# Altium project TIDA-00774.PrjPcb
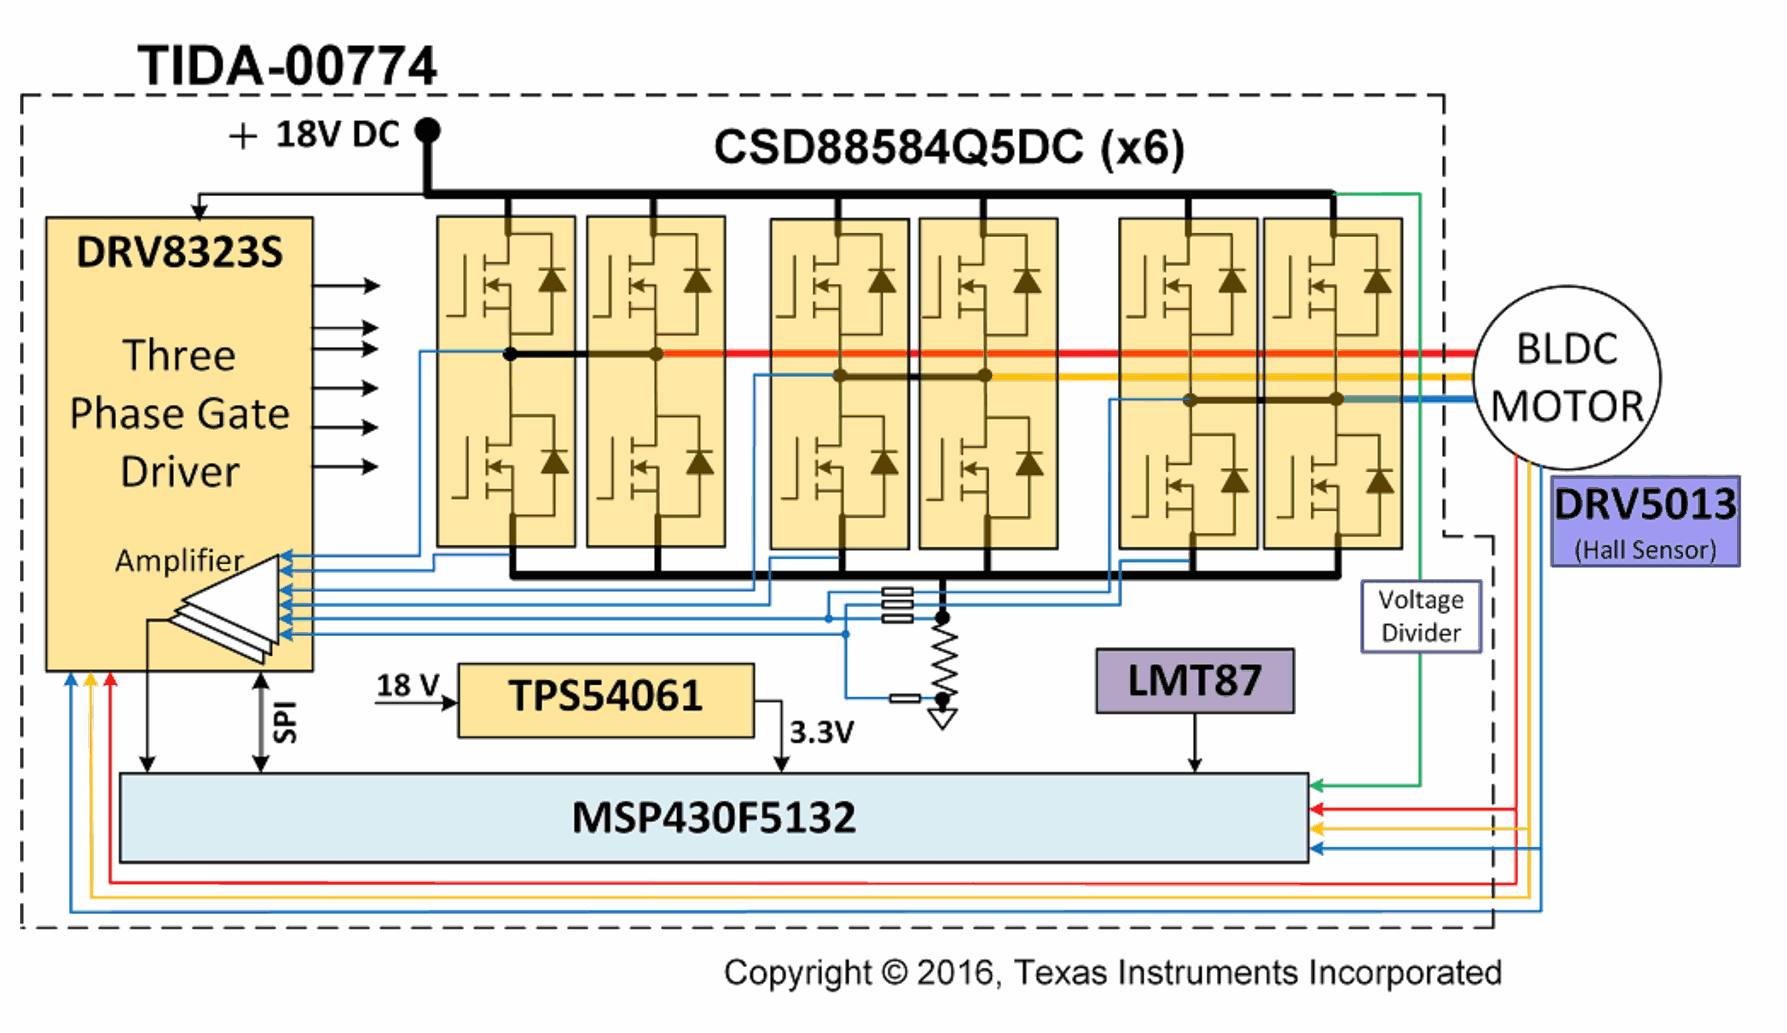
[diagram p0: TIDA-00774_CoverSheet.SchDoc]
CopyrightYear: 2016; EVM_orderable: N/A; PCB_Layout: Avinash N; PCB_Rev: E2; PRJ_Customer: Public Release; PRJ_Engineer: Manu Balakrishnan; PRJ_Number: TIDA-00774; PRJ_Title: 18V/1kW, 98% eff power stage for brushless motor; SCH_Rev: E2; TechSupport: http://www.ti.com/support; TID: 00774
5 sheets, 134 parts. Net scope: flat (ports and power ports of the same name join across sheets).
Board file: TIDA-00774.PcbDoc
Sheets:
  TIDA-00774_CoverSheet.SchDoc
  TIDA-00774_Page1.SchDoc
  TIDA-00774_Page2.SchDoc
  TIDA-00774_Page3.SchDoc
  TIDA-00774_Hardware.SchDoc

## Sheet TIDA-00774_CoverSheet.SchDoc
size 431 x 279 mm; Date: Not shown in title block; ApprovedBy: Not shown in title block; CheckedBy: Not shown in title block; Author: Not shown in title block; CompanyName: Not shown in title block; DrawnBy: Manu; Engineer: Not shown in title block; Organization: Not shown in title block; Address1: Not shown in title block; Address2: Not shown in title block; Address3: Not shown in title block; Address4: Not shown in title block; DocumentNumber: 1; Revision: Use project parameter SCH_Rev; SheetNumber: 1; SheetTotal: 5; PageSetup: Record=PageOptions¦CenterHorizontal=True¦CenterVertical=True¦PrintScale=1.00¦XCorrection=1.00¦YCorrection=1.00¦PrintKind=0¦BorderSize=5000000¦LeftOffset=0¦BottomOffset=0¦Orientation=2¦PaperLength=1000¦PaperWidth=1000¦Scale=100¦PaperSource=15¦PrintQuality=600¦MediaType=1¦DitherType=10¦PaperKind=Letter¦PrintScaleMode=1

## Sheet TIDA-00774_Page1.SchDoc
size 431 x 279 mm; Date: Not shown in title block; ApprovedBy: Not shown in title block; CheckedBy: Not shown in title block; Author: Not shown in title block; CompanyName: Not shown in title block; DrawnBy: Manu; Engineer: Not shown in title block; Organization: Not shown in title block; Address1: Not shown in title block; Address2: Not shown in title block; Address3: Not shown in title block; Address4: Not shown in title block; DocumentNumber: 1; Revision: Use project parameter SCH_Rev; SheetNumber: 2; SheetTotal: 5; PageSetup: Record=PageOptions¦CenterHorizontal=True¦CenterVertical=True¦PrintScale=1.00¦XCorrection=1.00¦YCorrection=1.00¦PrintKind=0¦BorderSize=5000000¦LeftOffset=0¦BottomOffset=0¦Orientation=2¦PaperLength=1000¦PaperWidth=1000¦Scale=100¦PaperSource=15¦PrintQuality=600¦MediaType=1¦DitherType=10¦PaperKind=Letter¦PrintScaleMode=1
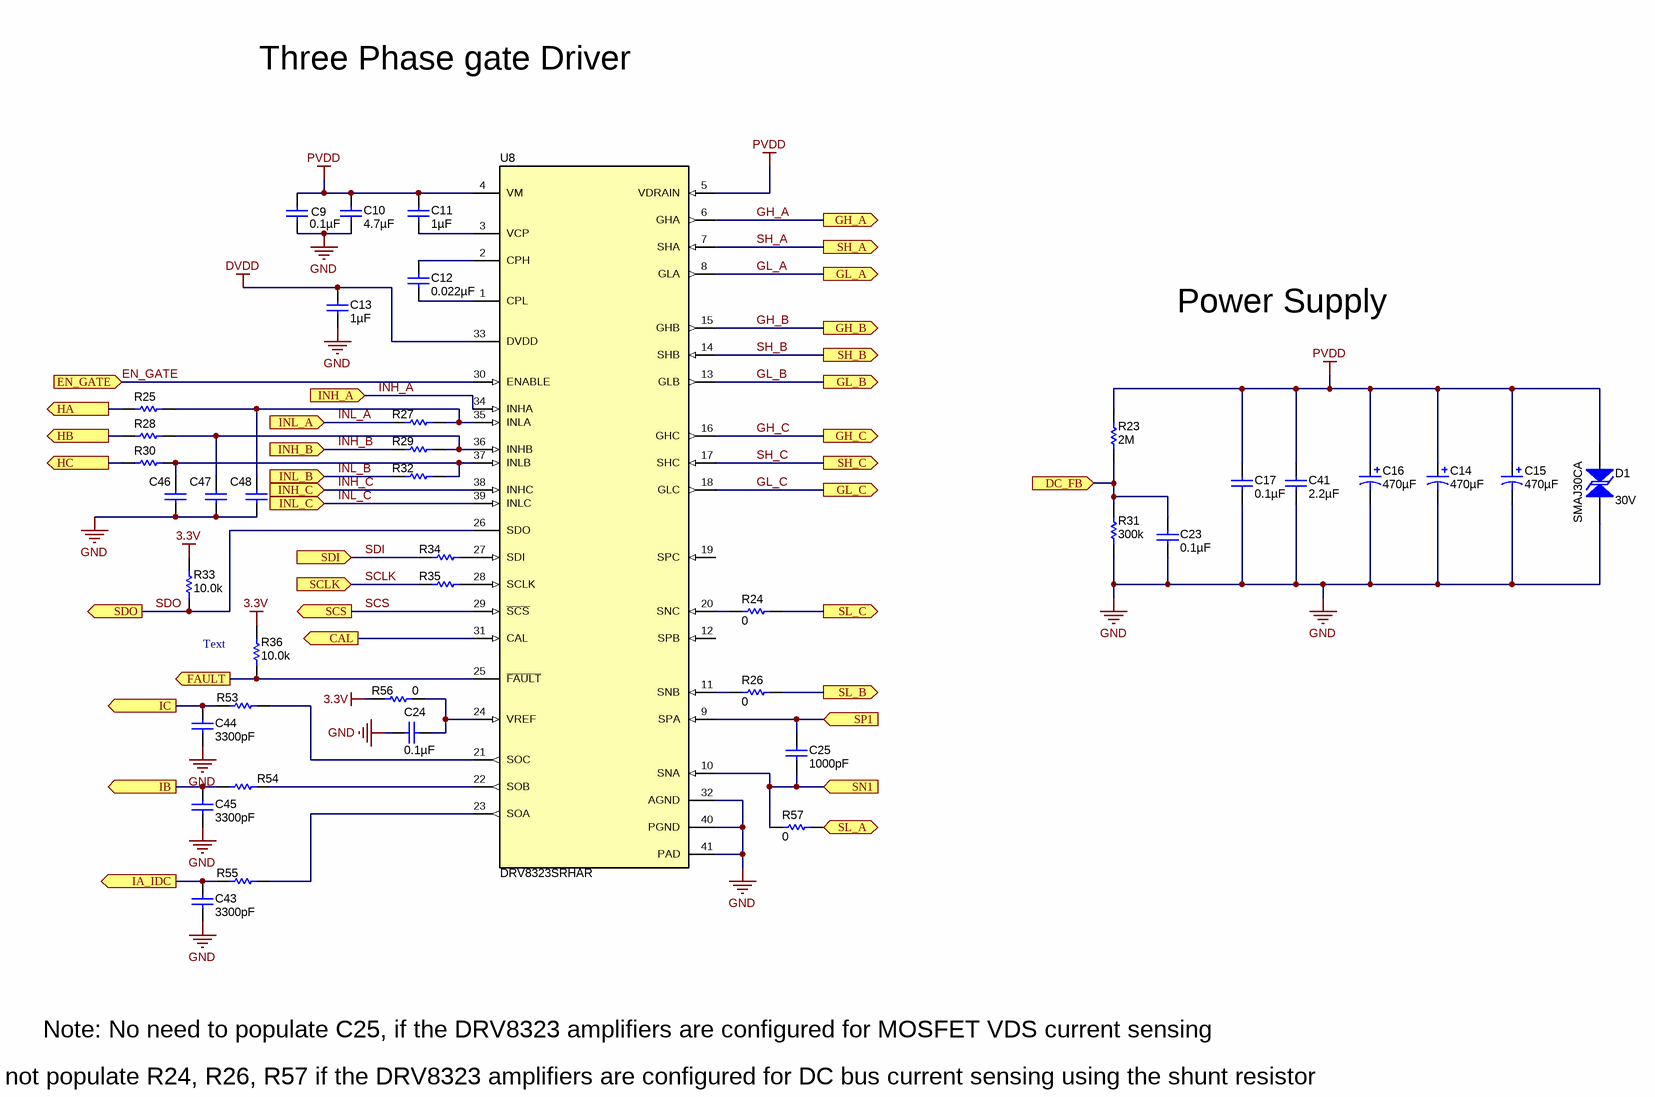
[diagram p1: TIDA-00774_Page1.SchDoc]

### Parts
C9  ValueDisplayed: 0.1µF  [0603]  (hidden comment: 06035C104KAT2A)
C10  ValueDisplayed: 4.7µF  [1206_180]  (hidden comment: GRM31CR71H475KA12L)
C11  ValueDisplayed: 1µF  [0603]  (hidden comment: C1608X7R1C105K)
C12  ValueDisplayed: 0.022µF  [0603]  (hidden comment: C0603C223K3RACTU)
C13  ValueDisplayed: 1µF  [0603]  (hidden comment: C1608X7R1C105K)
C14  ValueDisplayed: 470µF  [CAPPR5-10X20]  (hidden comment: 35ZLG470MEFC10X20)
C15  ValueDisplayed: 470µF  [CAPPR5-10X20]  (hidden comment: 35ZLG470MEFC10X20)
C16  ValueDisplayed: 470µF  [CAPPR5-10X20]  (hidden comment: 35ZLG470MEFC10X20)
C17  ValueDisplayed: 0.1µF  [0805_HV]  (hidden comment: C2012X7R1E104K)
C23  ValueDisplayed: 0.1µF  [0402]  (hidden comment: 885012105016)
C24  ValueDisplayed: 0.1µF  [0402]  (hidden comment: 885012105016)
C25  ValueDisplayed: 1000pF  [0402]  (hidden comment: 885012205061)
C41  ValueDisplayed: 2.2µF  [1210]  (hidden comment: GRM32ER72A225KA35L)
C43  ValueDisplayed: 3300pF  [0402]  (hidden comment: CGA2B2X7R1H332K050BA)
C44  ValueDisplayed: 3300pF  [0402]  (hidden comment: CGA2B2X7R1H332K050BA)
C45  ValueDisplayed: 3300pF  [0402]  (hidden comment: CGA2B2X7R1H332K050BA)
C46  885012205061  [0402]  (value not drawn)
C47  885012205061  [0402]  (value not drawn)
C48  885012205061  [0402]  (value not drawn)
D1  SMAJ30CA  value 30V  [SMA]
R23  ValueDisplayed: 2M  [0603]  (hidden comment: RC0603FR-0734K8L)
R24  ValueDisplayed: 0  [0402]  (hidden comment: CRCW04020000Z0ED)
R25  ERJ-2RKF1000X  [0402]  (value not drawn)
R26  ValueDisplayed: 0  [0402]  (hidden comment: CRCW04020000Z0ED)
R27  ERJ-2RKF1000X  [0402]  (value not drawn)
R28  ERJ-2RKF1000X  [0402]  (value not drawn)
R29  ERJ-2RKF1000X  [0402]  (value not drawn)
R30  ERJ-2RKF1000X  [0402]  (value not drawn)
R31  ValueDisplayed: 300k  [0402]  (hidden comment: ERJ-2RKF2201X)
R32  ERJ-2RKF1000X  [0402]  (value not drawn)
R33  ValueDisplayed: 10.0k  [0402]  (hidden comment: CRCW040210K0FKED)
R34  ERJ-2RKF1000X  [0402]  (value not drawn)
R35  ERJ-2RKF1000X  [0402]  (value not drawn)
R36  ValueDisplayed: 10.0k  [0402]  (hidden comment: CRCW040210K0FKED)
R53  ERJ-2RKF1000X  [0402]  (value not drawn)
R54  ERJ-2RKF1000X  [0402]  (value not drawn)
R55  ERJ-2RKF1000X  [0402]  (value not drawn)
R56  ValueDisplayed: 0  [0402]  (hidden comment: CRCW04020000Z0ED)
R57  ValueDisplayed: 0  [0402]  (hidden comment: CRCW04020000Z0ED)
U8  DRV8323SRHAR  [RHA0040B]

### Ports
CAL (out), DC_FB (in), EN_GATE (in), FAULT (out), GH_A (out), GH_B (out), GH_C (out), GL_A (out), GL_B (out), GL_C (out), HA (out), HB (out), HC (out), IA_IDC (out), IB (out), IC (out), INH_A (in), INH_B (in), INH_C (in), INL_A (in), INL_B (in), INL_C (in), SCLK (in), SCS (out), SDI (in), SDO (out), SH_A (out), SH_B (out), SH_C (out), SL_A (out), SL_B (out), SL_C (out), SN1 (in), SP1 (in)

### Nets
3.3V: R33.1 R36.1 R56.1
DVDD: C13.1 U8.33(DVDD)
GND: C9.2 C10.1 C13.2 C14.2(-) C15.2(-) C16.2(-) C17.2 C23.2 C24.2 C41.2 C43.2 C44.2 C45.2 C46.2 C47.2 C48.2 D1.1 R31.1 U8.32(AGND) U8.40(PGND) U8.41(PAD)
PVDD: C9.1 C10.2 C11.1 C14.1(+) C15.1(+) C16.1(+) C17.1 C41.1 D1.2 R23.2 U8.4(VM) U8.5(VDRAIN)
CAL: U8.31(CAL) ; port CAL
DC_FB: C23.1 R23.1 R31.2 ; port DC_FB
EN_GATE: U8.30(ENABLE) ; port EN_GATE
FAULT: R36.2 U8.25(~{FAULT}) ; port FAULT
GH_A: U8.6(GHA) ; port GH_A
GH_B: U8.15(GHB) ; port GH_B
GH_C: U8.16(GHC) ; port GH_C
GL_A: U8.8(GLA) ; port GL_A
GL_B: U8.13(GLB) ; port GL_B
GL_C: U8.18(GLC) ; port GL_C
HA: R25.1 ; port HA
HB: R28.1 ; port HB
HC: R30.1 ; port HC
IA_IDC: C43.1 R55.2 ; port IA_IDC
IB: C45.1 R54.2 ; port IB
IC: C44.1 R53.2 ; port IC
INH_A: U8.34(INHA) ; port INH_A
INH_B: R29.1 ; port INH_B
INH_C: U8.38(INHC) ; port INH_C
INL_A: R27.1 ; port INL_A
INL_B: R32.1 ; port INL_B
INL_C: U8.39(INLC) ; port INL_C
SCLK: R35.2 ; port SCLK
SCS: U8.29(~{SCS}) ; port SCS
SDI: R34.2 ; port SDI
SDO: R33.2 U8.26(SDO) ; port SDO
SH_A: U8.7(SHA) ; port SH_A
SH_B: U8.14(SHB) ; port SH_B
SH_C: U8.17(SHC) ; port SH_C
SL_A: R24.1 R26.1 R57.1 ; port SL_B, port SL_C, port SL_A
SN1: C25.2 R57.2 U8.10(SNA) ; port SN1
SP1: C25.1 U8.9(SPA) ; port SP1
NetC11_2: C11.2 U8.3(VCP)
NetC12_1: C12.1 U8.1(CPL)
NetC12_2: C12.2 U8.2(CPH)
NetC24_1: C24.1 R56.2 U8.24(VREF)
NetC46_1: C46.1 R30.2 R32.2 U8.37(INLB)
NetC47_1: C47.1 R28.2 R29.2 U8.36(INHB)
NetC48_1: C48.1 R25.2 R27.2 U8.35(INLA)
NetR24_2: R24.2 U8.20(SNC)
NetR26_2: R26.2 U8.11(SNB)
NetR34_1: R34.1 U8.27(SDI)
NetR35_1: R35.1 U8.28(SCLK)
NetR53_1: R53.1 U8.21(SOC)
NetR54_1: R54.1 U8.22(SOB)
NetR55_1: R55.1 U8.23(SOA)

Not connected (* = marked no-connect by the designer): U8 12(SPB) 19(SPC)

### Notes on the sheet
- Three Phase gate Driver
- Power Supply
- Text
- Note: No need to populate C25, if the DRV8323 amplifiers are configured for MOSFET VDS current sensing
- Do not populate R24, R26, R57 if the DRV8323 amplifiers are configured for DC bus current sensing using the shunt resistor

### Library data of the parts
C9 = 06035C104KAT2A: CAP, CERM, 0.1 µF, 50 V, +/- 10%, X7R, 0603; Manufacturer: AVX; Polarized: N; CompType: Capacitor; Value: 0.1uF; U/M: EA; Cap_F: 0.0000001; Tolerance_%: 10; Value1: Unknown; VDC_V: 50; Value2: 50V; TaMin_C: -55; TaMax_C: 125
C10 = GRM31CR71H475KA12L: CAP, CERM, 4.7 µF, 50 V, +/- 10%, X7R, 1206; Manufacturer: MuRata; Polarized: N; CompType: Capacitor; Value: 4.7uF; U/M: EA; Cap_F: 0.0000047; Tolerance_%: 10; Value1: Unknown; VDC_V: 50; Value2: 50V; TaMin_C: -55; TaMax_C: 125; Cap_Case: 2220; SizeArea_mm2: 5.12; SizeAreaWB_mm2: 10.92; SizeX_mm: 3.2; SizeY_mm: 1.6; SizeZ_mm: 1.8; AEC Category: Q200
C11 C13 = C1608X7R1C105K: CAP, CERM, 1 µF, 16 V, +/- 10%, X7R, 0603; Manufacturer: TDK; Polarized: N; CompType: Capacitor; Value: 1uF; U/M: EA; Cap_F: 0.000001; Tolerance_%: 10; ESR_ohm: 0.0057; Value1: 0.0057 ohm; VDC_V: 16; Value2: 16V; TaMin_C: -55; TaMax_C: 125; AEC Category: Q200
C12 = C0603C223K3RACTU: CAP, CERM, 0.022 µF, 25 V, +/- 10%, X7R, 0603; Manufacturer: Kemet; Polarized: N; CompType: Capacitor; Value: 0.022uF; U/M: EA; Cap_F: 0.000000022; Tolerance_%: 10; Value1: Unknown; VDC_V: 25; Value2: 25V; TaMin_C: -55; TaMax_C: 125
C14-C16 = 35ZL470MEFC10X20: 470µF 35V CAP ALUM CAN 4000 Hrs @ 105°C; Manufacturer: Rubycon; Polarized: Y; CompType: Capacitor; Value: 470uF; U/M: EA; Cap_F: 0.000470; Tolerance_%: 20; Value1: Unknown; VDC_V: 35; TaMin_C: -40; TaMax_C: 105; Cap_Case: 10x20; AEC Category: Q200; AEC Qualified: N
C17 = C2012X7R1E104K: CAP, CERM, 0.1 µF, 50 V, +/- 10%, X7R, 0805; PartNumber: 08055C104KAT2A; Manufacturer: AVX Corporation; Polarized: N; CompType: Capacitor; Value: 0.1uF; U/M: EA; Cap_F: 0.0000001; Tolerance_%: 10; Value1: Unknown; VDC_V: 50; Value2: 50V; TaMin_C: -55; TaMax_C: 125; Cap_Case: 0805; AEC Category: Q200
C23 = 885012105016: CAP, CERM, 0.1 µF, 16 V, +/- 20%, X5R, 0402; Manufacturer: Wurth Elektronik; Polarized: N; CompType: Capacitor; Value: 0.1uF; U/M: EA; Cap_F: 0.0000001; Tolerance_%: 20; Value1: Unknown; VDC_V: 16; Value2: 16V; TaMin_C: -55; TaMax_C: 85; AEC Category: Q200
C24 = 885012105016: CAP, CERM, 0.1 µF, 16 V, +/- 20%, X5R, 0402; Manufacturer: Wurth Elektronik; Polarized: N; CompType: Capacitor; Value: 0.1uF; U/M: EA; Cap_F: 0.0000001; Tolerance_%: 20; Value1: Unknown; VDC_V: 16; Value2: 16V; TaMin_C: -55; TaMax_C: 85; SizeArea_mm2: 0.5; SizeAreaWB_mm2: 3; SizeX_mm: 1; SizeZ_mm: 0.6; AEC Category: Q200
C25 C46-C48 = 885012205061: CAP, CERM, 1000 pF, 50 V, +/- 10%, X7R, 0402; Manufacturer: Wurth Elektronik; Polarized: N; CompType: Capacitor; Value: 1000pF; U/M: EA; Cap_F: 0.000000001; Tolerance_%: 10; Value1: Unknown; VDC_V: 50; Value2: 50V; TaMin_C: -55; TaMax_C: 125; AEC Category: Q200
C41 = GRM32ER72A225KA35L: CAP, CERM, 2.2 µF, 100 V, +/- 10%, X7R, 1210; Manufacturer: MuRata; Polarized: N; CompType: Capacitor; Value: 2.2uF; U/M: EA; Cap_F: 0.0000022; Tolerance_%: 10; ESR_ohm: 0.007; Value1: 0.007 ohm; VDC_V: 100; Value2: 100V; IRMS_A: 4.4; TaMin_C: -55; TaMax_C: 125; AEC Category: Q200
C43-C45 = CGA2B2X7R1H332K050BA: CAP, CERM, 3300 pF, 50 V, +/- 10%, X7R, AEC-Q200 Grade 1, 0402; Manufacturer: TDK; Polarized: N; CompType: Capacitor; Value: 3300pF; U/M: EA; Cap_F: 0.0000000033; Tolerance_%: 10; ESR_ohm: 0.785178; Value1: 0.785178 ohm; VDC_V: 50; Value2: 50V; IRMS_A: 0.272902; TaMin_C: -55; TaMax_C: 125; SizeArea_mm2: 0.5; SizeAreaWB_mm2: 3; SizeX_mm: 1; SizeZ_mm: 0.6; AEC Category: Q200; AEC Qualified: Y
D1 = SMAJ30CA: Diode, TVS, Bi, 30 V, 400 W, SMA; Manufacturer: Littelfuse; U/M: EA; Power_W: 400; Vr_V: 30; Value1: 400W; RJA_CperW: 120; AEC Category: Q101
R23 = RC0603FR-0734K8L: RES SMD 2M OHM 1% 1/10W 0603; PartNumber: RC0603FR-072ML; Manufacturer: Yageo; CompType: Resistor; Res_ohm: 34800; Tolerance_%: 1; Power_W: 0.1; Value2: 0.1W; VDC_V: 150; TempCo: 200 ppm/C; EIA_Code: E96; U/M: EA; AEC Category: Q200
R24 R26 R56 R57 = CRCW04020000Z0ED: RES, 0, 5%, 0.063 W, 0402; Manufacturer: Vishay-Dale; CompType: Resistor; Value: 0; Value_Code: 0000; Tolerance_%: 5; Power_W: 0.063; Value2: 0.063W; VDC_V: 50; TempCo: 200 ppm/C; SizeArea_mm2: 0.5; SizeX_mm: 1; SizeZ_mm: 0.6; EIA_Code: E24; U/M: EA; AEC Category: Q200
R25 R27-R30 R32 R34 R35 R53-R55 = ERJ-2RKF1000X: RES, 100, 1%, 0.1 W, 0402; Manufacturer: Panasonic; CompType: Resistor; Res_ohm: 100; Value: 100; Value_Code: 100R; Tolerance_%: 1; Power_W: 0.1; Value2: 0.1W; VDC_V: 50; TempCo: 100 ppm/C; EIA_Code: E96; U/M: EA; AEC Category: Q200
R31 = ERJ-2RKF2201X: RES SMD 300K OHM 1% 1/16W 0402; PartNumber: RC0402FR-07300KL; Manufacturer: Yageo; CompType: Resistor; Tolerance_%: 1; Power_W: 0.1; Value2: 0.063W; VDC_V: 50; TempCo: 100 ppm/C; U/M: EA; AEC Category: Q200
R33 R36 = CRCW040210K0FKED: RES, 10.0 k, 1%, 0.063 W, 0402; Manufacturer: Vishay-Dale; CompType: Resistor; Res_ohm: 10000; Value: 10.0k; Value_Code: 10k0; Tolerance_%: 1; Power_W: 0.063; Value2: 0.063W; VDC_V: 50; TempCo: 100 ppm/C; EIA_Code: E96; U/M: EA; AEC Category: Q200; SizeArea_mm2: 0.5; SizeZ_mm: 0.6
U8 = DRV8323SRHAR: 60-V Three-Phase Smart Gate Driver, RHA0040B; Alternate PartNumber: DRV8323SRHAT; Manufacturer: Texas Instruments; SymbolCreator: Altium; SizeArea_mm2: 37.8225; SizeAreaWB_mm2: 66.4225; SizeX_mm: 6.15; SizeZ_mm: 1; CompType: IC; U/M: EA

## Sheet TIDA-00774_Page2.SchDoc
size 431 x 279 mm; Date: Not shown in title block; ApprovedBy: Not shown in title block; CheckedBy: Not shown in title block; Author: Not shown in title block; CompanyName: Not shown in title block; DrawnBy: Manu; Engineer: Not shown in title block; Organization: Not shown in title block; Address1: Not shown in title block; Address2: Not shown in title block; Address3: Not shown in title block; Address4: Not shown in title block; DocumentNumber: 1; Revision: Use project parameter SCH_Rev; SheetNumber: 3; SheetTotal: 5; PageSetup: Record=PageOptions¦CenterHorizontal=True¦CenterVertical=True¦PrintScale=1.00¦XCorrection=1.00¦YCorrection=1.00¦PrintKind=0¦BorderSize=5000000¦LeftOffset=0¦BottomOffset=0¦Orientation=2¦PaperLength=1000¦PaperWidth=1000¦Scale=100¦PaperSource=15¦PrintQuality=600¦MediaType=1¦DitherType=10¦PaperKind=Letter¦PrintScaleMode=1
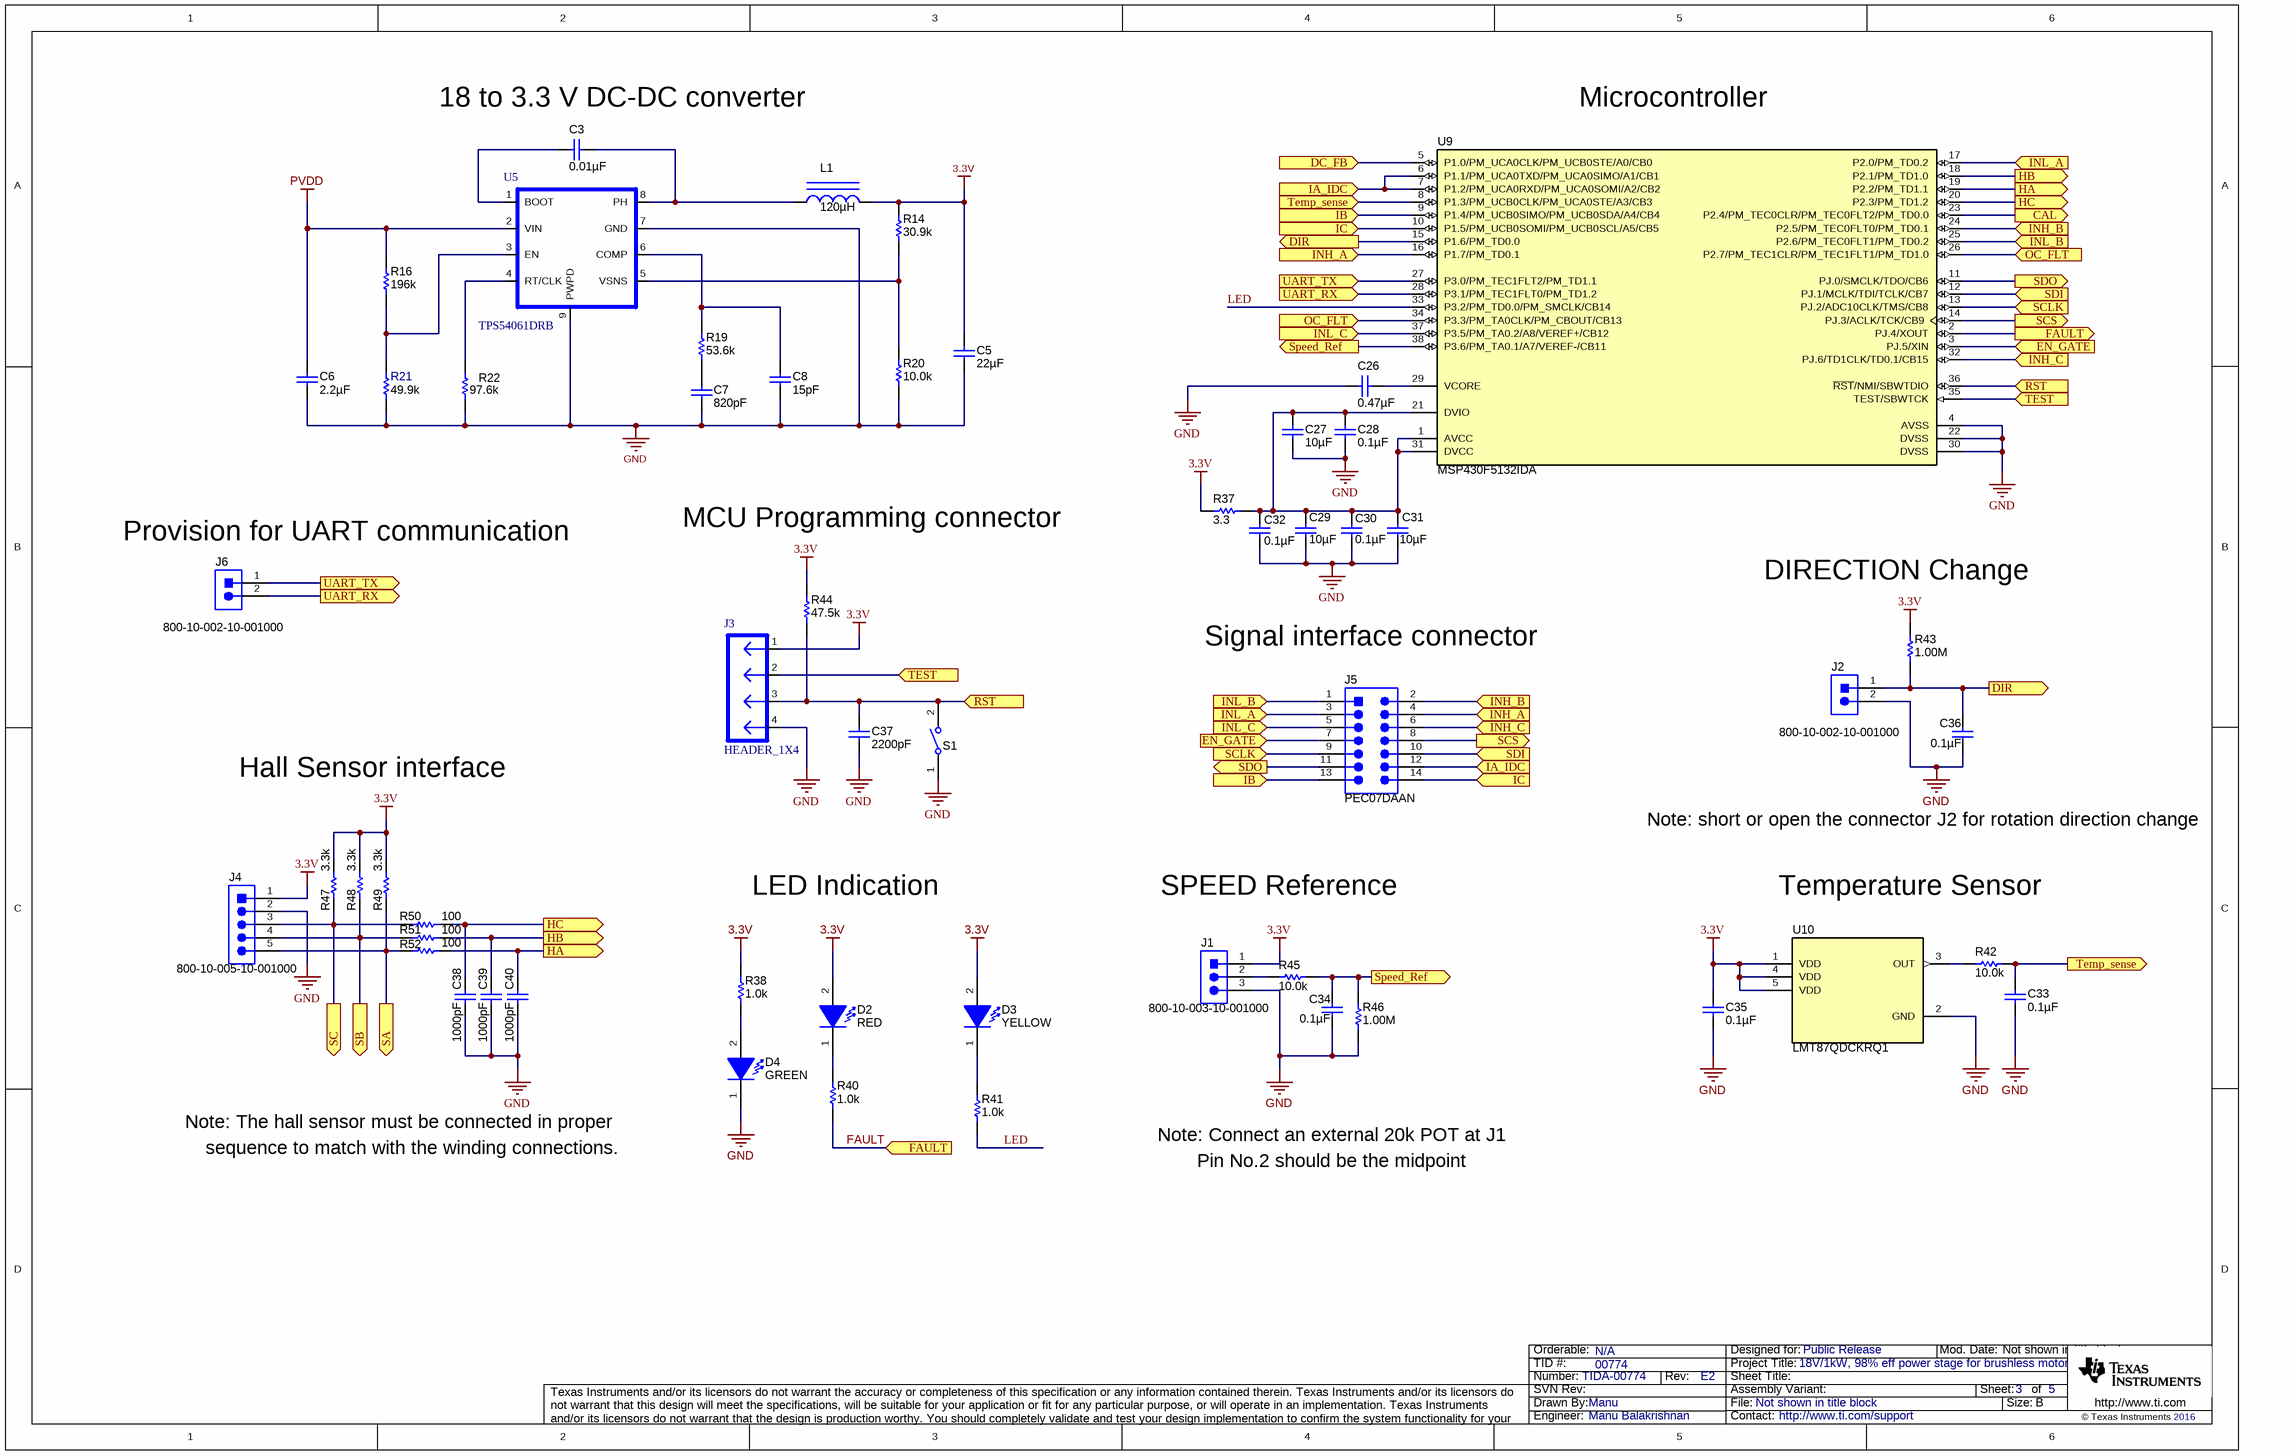
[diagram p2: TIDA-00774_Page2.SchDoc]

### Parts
C3  ValueDisplayed: 0.01µF  [0402]  (hidden comment: GRM155R71E103KA01D)
C5  ValueDisplayed: 22µF  [1210_270]  (hidden comment: TMK325B7226KMHT)
C6  ValueDisplayed: 2.2µF  [1210]  (hidden comment: GRM32ER72A225KA35L)
C7  ValueDisplayed: 820pF  [0402]  (hidden comment: GRM155R71H821KA01D)
C8  ValueDisplayed: 15pF  [0402]  (hidden comment: CC0402JRNPO9BN150)
C26  ValueDisplayed: 0.47µF  [0805_HV]  (hidden comment: C0805C474K4RACTU)
C27  ValueDisplayed: 10µF  [0805_HV]  (hidden comment: 0805YD106MAT2A)
C28  ValueDisplayed: 0.1µF  [0603]  (hidden comment: 0603YC104JAT2A)
C29  ValueDisplayed: 10µF  [0805_HV]  (hidden comment: 0805YD106MAT2A)
C30  ValueDisplayed: 0.1µF  [0603]  (hidden comment: 0603YC104JAT2A)
C31  ValueDisplayed: 10µF  [0805_HV]  (hidden comment: 0805YD106MAT2A)
C32  ValueDisplayed: 0.1µF  [0603]  (hidden comment: 0603YC104JAT2A)
C33  ValueDisplayed: 0.1µF  [0402]  (hidden comment: 885012105016)
C34  ValueDisplayed: 0.1µF  [0402]  (hidden comment: 885012105016)
C35  ValueDisplayed: 0.1µF  [0402]  (hidden comment: 885012105016)
C36  ValueDisplayed: 0.1µF  [0402]  (hidden comment: 885012105016)
C37  ValueDisplayed: 2200pF  [0402]  (hidden comment: GRM155R71H222KA01D)
C38  ValueDisplayed: 1000pF  [0402]  (hidden comment: 885012205061)
C39  ValueDisplayed: 1000pF  [0402]  (hidden comment: 885012205061)
C40  ValueDisplayed: 1000pF  [0402]  (hidden comment: 885012205061)
D2  value RED  [WL-SMCW_GREEN]  (hidden comment: 150060GS75000)
D3  value YELLOW  [WL-SMCW_GREEN]  (hidden comment: 150060GS75000)
D4  value GREEN  [WL-SMCW_GREEN]  (hidden comment: 150060GS75000)
J1  800-10-003-10-001000  [Mill-Max_800-10-003-10-001000]
J2  800-10-002-10-001000  [Mill-Max_800-10-002-10-001000]
J3  HEADER_1X4  [Mill-Max_800-10-004-10-001000]
J4  800-10-005-10-001000  [Mill-Max_800-10-005-10-001000]
J5  PEC07DAAN  [CONN_PEC07DAAN]
J6  800-10-002-10-001000  [Mill-Max_800-10-002-10-001000]
L1  ValueDisplayed: 120µH  [SDR0302]  (hidden comment: SDR0302-121KL)
R14  value 30.9k  [0402]  (hidden comment: CRCW040230K9FKED)
R16  ValueDisplayed: 196k  [0402]  (hidden comment: CRCW0402196KFKED)
R19  ValueDisplayed: 53.6k  [0402]  (hidden comment: CRCW040253K6FKED)
R20  value 10.0k  [0402]  (hidden comment: CRCW040210K0FKED)
R21  ValueDisplayed: 49.9k  [0402]  (hidden comment: CRCW040249K9FKED)
R22  value 97.6k  [0402]  (hidden comment: CRCW040297K6FKED)
R37  ValueDisplayed: 3.3  [0603]  (hidden comment: CRCW06033R30JNEA)
R38  ValueDisplayed: 1.0k  [0603]  (hidden comment: CRCW06031K00JNEA)
R40  ValueDisplayed: 1.0k  [0603]  (hidden comment: CRCW06031K00JNEA)
R41  ValueDisplayed: 1.0k  [0603]  (hidden comment: CRCW06031K00JNEA)
R42  ValueDisplayed: 10.0k  [0402]  (hidden comment: CRCW040210K0FKED)
R43  ValueDisplayed: 1.00M  [0402]  (hidden comment: ERJ-2RKF1004X)
R44  ValueDisplayed: 47.5k  [0402]  (hidden comment: CRCW040247K5FKED)
R45  ValueDisplayed: 10.0k  [0402]  (hidden comment: CRCW040210K0FKED)
R46  ValueDisplayed: 1.00M  [0402]  (hidden comment: ERJ-2RKF1004X)
R47  ValueDisplayed: 3.3k  [0402]  (hidden comment: CRCW04023K30JNED)
R48  ValueDisplayed: 3.3k  [0402]  (hidden comment: CRCW04023K30JNED)
R49  ValueDisplayed: 3.3k  [0402]  (hidden comment: CRCW04023K30JNED)
R50  ValueDisplayed: 100  [0402]  (hidden comment: ERJ-2RKF1000X)
R51  ValueDisplayed: 100  [0402]  (hidden comment: ERJ-2RKF1000X)
R52  ValueDisplayed: 100  [0402]  (hidden comment: ERJ-2RKF1000X)
S1  434121025816  [SW_434121025816]  (value not drawn)
U5  TPS54061DRB  [DRB0008B]
U9  MSP430F5132IDA  [DA0038A_N]
U10  LMT87QDCKRQ1  [DCK0005A_N]

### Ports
CAL (out), DC_FB (in), DIR (out), EN_GATE (in), FAULT (in), FAULT (out), HA (out), HB (out), HC (out), IA_IDC (in), IB (in), IC (in), INH_A (in), INH_B (in), INH_C (in), INL_A (in), INL_B (in), INL_C (in), OC_FLT (in), RST (in), SA (out), SB (out), SC (out), SCLK (in), SCS (out), SDI (in), SDO (out), Speed_Ref (out), Temp_sense (in), Temp_sense (out), TEST (in), UART_RX (in), UART_RX (out), UART_TX (in), UART_TX (out)

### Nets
3.3V: C5.1 C35.1 D2.2(A) D3.2(A) J1.1 J3.1 J4.1 L1.2 R14.2 R37.1 R38.2 R43.1 R44.2 R47.2 R48.2 R49.2 U10.1(VDD) U10.4(VDD) U10.5(VDD)
GND: C5.2 C6.2 C7.2 C8.2 C26.2 C27.2 C28.2 C29.2 C30.2 C31.2 C32.2 C33.2 C34.2 C35.2 C36.2 C37.2 C38.2 C39.2 C40.2 D4.1(K) J1.3 J2.2 J3.4 J4.2 R20.1 R21.1 R22.1 R46.1 S1.1 U5.7(GND) U5.9(PWPD) U9.4(AVSS) U9.22(DVSS) U9.30(DVSS) U10.2(GND)
PVDD: C6.1 R16.2 U5.2(VIN)
CAL: U9.23(P2.4/PM_TEC0CLR/PM_TEC0FLT2/PM_TD0.0) ; port CAL
DC_FB: U9.5(P1.0/PM_UCA0CLK/PM_UCB0STE/A0/CB0) ; port DC_FB
DIR: C36.1 J2.1 R43.2 U9.15(P1.6/PM_TD0.0) ; port DIR
EN_GATE: J5.7 U9.3(PJ.5/XIN) ; port EN_GATE
FAULT: R40.1 U9.2(PJ.4/XOUT) ; port FAULT
HA: C40.1 R52.1 U9.19(P2.2/PM_TD1.1) ; port HA
HB: C39.1 R51.1 U9.18(P2.1/PM_TD1.0) ; port HB
HC: C38.1 R50.1 U9.20(P2.3/PM_TD1.2) ; port HC
IA_IDC: J5.12 U9.6(P1.1/PM_UCA0TXD/PM_UCA0SIMO/A1/CB1) U9.7(P1.2/PM_UCA0RXD/PM_UCA0SOMI/A2/CB2) ; port IA_IDC
IB: J5.13 U9.9(P1.4/PM_UCB0SIMO/PM_UCB0SDA/A4/CB4) ; port IB
IC: J5.14 U9.10(P1.5/PM_UCB0SOMI/PM_UCB0SCL/A5/CB5) ; port IC
INH_A: J5.4 U9.16(P1.7/PM_TD0.1) ; port INH_A
INH_B: J5.2 U9.24(P2.5/PM_TEC0FLT0/PM_TD0.1) ; port INH_B
INH_C: J5.6 U9.32(PJ.6/TD1CLK/TD0.1/CB15) ; port INH_C
INL_A: J5.3 U9.17(P2.0/PM_TD0.2) ; port INL_A
INL_B: J5.1 U9.25(P2.6/PM_TEC0FLT1/PM_TD0.2) ; port INL_B
INL_C: J5.5 U9.37(P3.5/PM_TA0.2/A8/VEREF+/CB12) ; port INL_C
LED: R41.1 U9.33(P3.2/PM_TD0.0/PM_SMCLK/CB14)
OC_FLT: U9.26(P2.7/PM_TEC1CLR/PM_TEC1FLT1/PM_TD1.0) U9.34(P3.3/PM_TA0CLK/PM_CBOUT/CB13) ; port OC_FLT
RST: C37.1 J3.3 R44.1 S1.2 U9.36(~{RST}/NMI/SBWTDIO) ; port RST
SA: J4.5 R49.1 R52.2 ; port SA
SB: J4.4 R48.1 R51.2 ; port SB
SC: J4.3 R47.1 R50.2 ; port SC
SCLK: J5.9 U9.13(PJ.2/ADC10CLK/TMS/CB8) ; port SCLK
SCS: J5.8 U9.14(PJ.3/ACLK/TCK/CB9) ; port SCS
SDI: J5.10 U9.12(PJ.1/MCLK/TDI/TCLK/CB7) ; port SDI
SDO: J5.11 U9.11(PJ.0/SMCLK/TDO/CB6) ; port SDO
Speed_Ref: C34.1 R45.1 R46.2 U9.38(P3.6/PM_TA0.1/A7/VEREF-/CB11) ; port Speed_Ref
Temp_sense: C33.1 R42.1 U9.8(P1.3/PM_UCB0CLK/PM_UCA0STE/A3/CB3) ; port Temp_sense
TEST: J3.2 U9.35(TEST/SBWTCK) ; port TEST
UART_RX: J6.2 U9.28(P3.1/PM_TEC1FLT0/PM_TD1.2) ; port UART_RX
UART_TX: J6.1 U9.27(P3.0/PM_TEC1FLT2/PM_TD1.1) ; port UART_TX
NetC3_1: C3.1 L1.1 U5.8(PH)
NetC3_2: C3.2 U5.1(BOOT)
NetC7_1: C7.1 R19.1
NetC8_1: C8.1 R19.2 U5.6(COMP)
NetC26_1: C26.1 U9.29(VCORE)
NetC27_1: C27.1 C28.1 C29.1 C30.1 C31.1 C32.1 R37.2 U9.1(AVCC) U9.21(DVIO) U9.31(DVCC)
NetD2_1: D2.1(K) R40.2
NetD3_1: D3.1(K) R41.2
NetD4_2: D4.2(A) R38.1
NetJ1_2: J1.2 R45.2
NetR14_1: R14.1 R20.2 U5.5(VSNS)
NetR16_1: R16.1 R21.2 U5.3(EN)
NetR22_2: R22.2 U5.4(RT/CLK)
NetR42_2: R42.2 U10.3(OUT)

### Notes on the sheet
- (near C3) 18 to 3.3 V DC-DC converter
- (near U9) Microcontroller
- (near J6) Provision for UART communication
- MCU Programming connector
- (near R43) DIRECTION Change
- (near J5) Signal interface connector
- Hall Sensor interface
- Note: short or open the connector J2 for rotation direction change
- LED Indication
- SPEED Reference
- Temperature Sensor
- Note: The hall sensor must be connected in proper
- sequence to match with the winding connections.
- Note: Connect an external 20k POT at J1
- Pin No.2 should be the midpoint

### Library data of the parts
C3 = GRM155R71E103KA01D: CAP, CERM, 0.01 µF, 25 V, +/- 10%, X7R, 0402; Manufacturer: MuRata; Polarized: N; CompType: Capacitor; Value: 0.01uF; U/M: EA; Cap_F: 0.00000001; Tolerance_%: 10; Value1: Unknown; VDC_V: 25; Value2: 25V; TaMin_C: -55; TaMax_C: 125; SizeArea_mm2: 0.5; SizeAreaWB_mm2: 3; SizeX_mm: 1; SizeZ_mm: 0.6; AEC Category: Q200
C5 = TMK325B7226KMHT: CAP, CERM, 22 µF, 25 V, +/- 10%, X7R, AEC-Q200 Grade 1, 1210; Manufacturer: Taiyo Yuden; Polarized: N; CompType: Capacitor; Value: 22uF; U/M: EA; Cap_F: 0.000022; Tolerance_%: 10; Value1: Unknown; VDC_V: 25; Value2: 25V; TaMin_C: -55; TaMax_C: 125; Cap_Case: 1210; SizeArea_mm2: 8; SizeAreaWB_mm2: 14.7; SizeX_mm: 3.2; SizeY_mm: 2.5; SizeZ_mm: 2.7; AEC Category: Q200; AEC Qualified: Y; AEC Grade: 1
C6 = GRM32ER72A225KA35L: CAP, CERM, 2.2uF, 100V, +/-10%, X7R, 1210; Manufacturer: MuRata; Polarized: N; CompType: Capacitor; U/M: EA; Cap_F: 0.0000022; Tolerance_%: 10; ESR_Ohm: 0.007; Value1: 0.007 ohm; VDC_V: 100; IRMS_A: 4.4; TaMin_C: -55; TaMax_C: 125
C7 = GRM155R71H821KA01D: CAP, CERM, 820 pF, 50 V, +/- 10%, X7R, 0402; Manufacturer: MuRata; Polarized: N; CompType: Capacitor; Value: 820pF; U/M: EA; Cap_F: 0.00000000082; Tolerance_%: 10; Value1: Unknown; VDC_V: 50; Value2: 50V; TaMin_C: -55; TaMax_C: 125; SizeArea_mm2: 0.5; SizeAreaWB_mm2: 3; SizeX_mm: 1; SizeZ_mm: 0.6; AEC Category: Q200
C8 = CC0402JRNPO9BN150: CAP, CERM, 15 pF, 50 V, +/- 5%, C0G/NP0, 0402; Manufacturer: Yageo America; Polarized: N; CompType: Capacitor; Value: 15pF; U/M: EA; Cap_F: 0.000000000015; Tolerance_%: 5; Value1: Unknown; VDC_V: 50; Value2: 50V; TaMin_C: -55; TaMax_C: 125; SizeArea_mm2: 0.5; SizeAreaWB_mm2: 3; SizeX_mm: 1; SizeZ_mm: 0.6; AEC Category: Q200
C26 = C0805C474K4RACTU: CAP, CERM, 0.47 µF, 16 V, +/- 10%, X7R, 0805; Manufacturer: Kemet; Polarized: N; CompType: Capacitor; Value: 0.47uF; U/M: EA; Cap_F: 0.00000047; Tolerance_%: 10; Value1: Unknown; VDC_V: 16; Value2: 16V; TaMin_C: -55; TaMax_C: 125; Cap_Case: 0805
C27 C29 C31 = 0805YD106MAT2A: CAP, CERM, 10uF, 16V, +/-20%, X5R, 0805; Manufacturer: AVX; Polarized: N; CompType: Capacitor; U/M: EA; Cap_F: 0.00001; Tolerance_%: 20; Value1: Unknown; VDC_V: 16; TaMin_C: -55; TaMax_C: 85; Cap_Case: 0805
C28 C30 C32 = 0603YC104JAT2A: CAP, CERM, 0.1 µF, 16 V, +/- 5%, X7R, 0603; Manufacturer: AVX; Polarized: N; CompType: Capacitor; Value: 0.1uF; U/M: EA; Cap_F: 0.0000001; Tolerance_%: 5; ESR_ohm: 0.039; Value1: 0.039 ohm; VDC_V: 16; Value2: 16V; TaMin_C: -55; TaMax_C: 125
C33-C36 = 885012105016: as C23 on sheet TIDA-00774_Page1
C37 = GRM155R71H222KA01D: CAP, CERM, 2200 pF, 50 V, +/- 10%, X7R, 0402; Manufacturer: MuRata; Polarized: N; CompType: Capacitor; Value: 2200pF; U/M: EA; Cap_F: 0.0000000022; Tolerance_%: 10; Value1: Unknown; VDC_V: 50; Value2: 50V; TaMin_C: -55; TaMax_C: 125; AEC Category: Q200
C38-C40 = 885012205061: as C25 on sheet TIDA-00774_Page1
D2 = 150060GS75000: LED RED CLEAR 0603 SMD; Manufacturer: Wurth Elektronics Inc; PartNumber: 150060RS75000; Type: InGaN; Vf_V: 3.2; Value2: 2V; Io_A: 0.02; Tjmax_C: 85; Value1: W; Angle: 140; U/M: EA
D3 = 150060GS75000: LED YELLOW CLEAR 0603 SMD; Manufacturer: Wurth Elektronics Inc; PartNumber: 150060YS75000; Type: InGaN; Vf_V: 2V; Io_A: 0.02; Tjmax_C: 85; Value1: W; Angle: 140; U/M: EA
D4 = 150060GS75000: LED, Green, SMD; Manufacturer: Wurth Elektronics Inc; Type: InGaN; Vf_V: 3.2; Value2: 3.2V; Io_A: 0.02; Tjmax_C: 85; Value1: W; Angle: 140; U/M: EA
J1 = 800-10-003-10-001000: Header, 100mil, 3x1, TH; Manufacturer: Mill-Max; SymbolCreator: a0799628; U/M: EA
J2 J6 = 800-10-002-10-001000: Header, 100mil, 2x1, TH; Manufacturer: Mill-Max; SymbolCreator: a0412235; U/M: EA
J3 = HEADER_1X4: Header, Male 4-pin, 100mil spacing,; Manufacturer: Sullins; PartNumber: PEC04SAAN; area: 44000; Value: PEC04SAAN
J4 = 800-10-005-10-001000: Header, 100mil, 5x1, TH; Manufacturer: Mill-Max; SymbolCreator: a0412235
J5 = PEC07DAAN: Header, 100mil, 7x2, Tin, TH; Manufacturer: Sullins Connector Solutions; SymbolCreator: a0412235; Pitch_mm: 2.54; Gender: Male; Shrouded: N; Row_Count: 2; Current_A: 3; Voltage_V: 1800; Cert_UL: Y
L1 = SDR0302-121KL: Inductor, Drum Core, Ferrite, 120uH, 0.22A, 3.2 ohm, SMD; Manufacturer: Bourns; Ind_H: 120.0E-6; Imax_A: 0.22; Irms: 0.22A @ 40C rise; Isat: 0.29A @ 10% inductance drop; DCR_ohm: 3.2; Value1: 3.2 ohm
R14 = CRCW040230K9FKED: RES, 30.9k ohm, 1%, 0.063W, 0402; Manufacturer: Vishay-Dale; CompType: Resistor; Res_ohm: 30900; Value_Code: 30k9; Tolerance_%: 1; Power_W: 0.063; VDC_V: 50; TempCo: 100 ppm/C; EIA_Code: E96; U/M: EA
R16 = CRCW0402196KFKED: RES, 196 k, 1%, 0.063 W, 0402; Manufacturer: Vishay-Dale; CompType: Resistor; Value: 196k; Res_ohm: 196000; Tolerance_%: 1; Power_W: 0.063; Value2: 0.063W; VDC_V: 50; TempCo: 100 ppm/C; EIA_Code: E96; U/M: EA; SizeArea_mm2: 0.5; SizeZ_mm: 0.6; AEC Category: Q200
R19 = CRCW040253K6FKED: RES, 53.6 k, 1%, 0.063 W, 0402; Manufacturer: Vishay-Dale; CompType: Resistor; Value: 53.6k; Res_ohm: 53600; Value_Code: 53k6; Tolerance_%: 1; Power_W: 0.063; Value2: 0.063W; VDC_V: 50; TempCo: 100 ppm/C; EIA_Code: E96; U/M: EA; SizeArea_mm2: 0.5; SizeZ_mm: 0.6; AEC Category: Q200
R20 = CRCW040210K0FKED: RES, 10.0k ohm, 1%, 0.063W, 0402; Manufacturer: Vishay-Dale; CompType: Resistor; Res_ohm: 10000; Value_Code: 10k0; Tolerance_%: 1; Power_W: 0.063; VDC_V: 50; TempCo: 100 ppm/C; EIA_Code: E96; U/M: EA
R21 = CRCW040249K9FKED: RES, 49.9 k, 1%, 0.063 W, 0402; Manufacturer: Vishay-Dale; CompType: Resistor; Res_ohm: 49900; Value: 49.9k; Value_Code: 49k9; Tolerance_%: 1; Power_W: 0.063; Value2: 0.063W; VDC_V: 50; TempCo: 100 ppm/C; EIA_Code: E96; U/M: EA; SizeArea_mm2: 0.5; SizeZ_mm: 0.6; AEC Category: Q200
R22 = CRCW040297K6FKED: RES, 97.6k ohm, 1%, 0.063W, 0402; Manufacturer: Vishay-Dale; CompType: Resistor; Res_ohm: 97600; Value_Code: 97k6; Tolerance_%: 1; Power_W: 0.063; VDC_V: 50; TempCo: 100 ppm/C; EIA_Code: E96; U/M: EA
R37 = CRCW06033R30JNEA: RES, 3.3, 5%, 0.1 W, 0603; Manufacturer: Vishay-Dale; CompType: Resistor; Value: 3.3; Value_Code: 3R30; Tolerance_%: 5; Power_W: 0.1; Value2: 0.1W; VDC_V: 75; TempCo: 200 ppm/C; EIA_Code: E24; U/M: EA; SizeArea_mm2: 1.28; SizeX_mm: 1.6; SizeY_mm: 0.8; SizeZ_mm: 1; AEC Category: Q200
R38 R40 R41 = CRCW06031K00JNEA: RES, 1.0 k, 5%, 0.1 W, 0603; Manufacturer: Vishay-Dale; CompType: Resistor; Value: 1.0k; Res_ohm: 1000; Value_Code: 1k00; Tolerance_%: 5; Power_W: 0.1; Value2: 0.1W; VDC_V: 75; TempCo: 200 ppm/C; EIA_Code: E24; U/M: EA; AEC Category: Q200; SizeArea_mm2: 1.28; SizeX_mm: 1.6; SizeY_mm: 0.8; SizeZ_mm: 1
R42 R45 = CRCW040210K0FKED: RES, 10.0 k, 1%, 0.063 W, 0402; Manufacturer: Vishay-Dale; CompType: Resistor; Value: 10.0k; Res_ohm: 10000; Value_Code: 10k0; Tolerance_%: 1; Power_W: 0.063; Value2: 0.063W; VDC_V: 50; TempCo: 100 ppm/C; EIA_Code: E96; U/M: EA; AEC Category: Q200; SizeArea_mm2: 0.5; SizeZ_mm: 0.6
R43 R46 = ERJ-2RKF1004X: RES, 1.00 M, 1%, 0.1 W, 0402; Manufacturer: Panasonic; CompType: Resistor; Value: 1.00Meg; Res_ohm: 1000000; Value_Code: 1M00; Tolerance_%: 1; Power_W: 0.1; Value2: 0.1W; VDC_V: 50; TempCo: 100 ppm/C; EIA_Code: E96; U/M: EA; AEC Category: Q200
R44 = CRCW040247K5FKED: RES, 47.5 k, 1%, 0.063 W, 0402; Manufacturer: Vishay-Dale; CompType: Resistor; Value: 47.5k; Res_ohm: 47500; Value_Code: 47k5; Tolerance_%: 1; Power_W: 0.063; Value2: 0.063W; VDC_V: 50; TempCo: 100 ppm/C; EIA_Code: E96; U/M: EA; AEC Category: Q200
R47-R49 = CRCW04023K30JNED: RES, 3.3 k, 5%, 0.063 W, 0402; Manufacturer: Vishay-Dale; CompType: Resistor; Value: 3.3k; Res_ohm: 3300; Value_Code: 3k30; Tolerance_%: 5; Power_W: 0.063; Value2: 0.063W; VDC_V: 50; TempCo: 200 ppm/C; EIA_Code: E24; U/M: EA; AEC Category: Q200
R50-R52 = ERJ-2RKF1000X: RES, 100, 1%, 0.1 W, 0402; Manufacturer: Panasonic; CompType: Resistor; Value: 100; Value_Code: 100R; Tolerance_%: 1; Power_W: 0.1; Value2: 0.1W; VDC_V: 50; TempCo: 100 ppm/C; EIA_Code: E96; U/M: EA; AEC Category: Q200
S1 = 434121025816: Switch, Tactile, SPST, 12 V, SMD; Manufacturer: Wurth Elektronik; SymbolCreator: a0799628; VDC_V: 12; SwitchFunction: Off-On; PositionCount: 1; CurrentRating_mA: 50
U5 = TPS54061DRB: IC, 60V/0.2A  Synchronous Buck Regulator; Manufacturer: TI; Alternate Manufacturer: None; Area: 35344
U9 = MSP430F5132IDA: 25 MHz Mixed Signal Microcontroller with 8 KB Flash, 1024 B SRAM and 29 GPIOs, -40 to 85 degC, 38-pin SOP (DA), Green (RoHS & no Sb/Br); Alternate Manufacturer: Texas Instruments; Alternate PartNumber: Equivalent; ADC: 10-bit SAR; ADC Channels: 8; Brown Out Reset: Yes; DMA: 3; Frequency(MHz): 25; GPIO: 29; Multiplier: 32x32; Pin/Package: 38TSSOP, 40WQFN; SRAM(B): 1024; SubFamily: 5 Series; USCI_A (UART/LIN/IrDA/SPI): 1
U10 = LMT87QDCKRQ1: SC70 Analog Temperature Sensor with Class-AB Output, DCK0005A; Alternate PartNumber: LMT87QDCKTQ1; Manufacturer: Texas Instruments; SymbolCreator: a0411947; SizeArea_mm2: 4.2; SizeAreaWB_mm2: 9.3; SizeX_mm: 2.1; SizeY_mm: 2; SizeZ_mm: 1.1; CompType: IC; U/M: EA

## Sheet TIDA-00774_Page3.SchDoc
size 431 x 279 mm; Date: Not shown in title block; ApprovedBy: Not shown in title block; CheckedBy: Not shown in title block; Author: Not shown in title block; CompanyName: Not shown in title block; DrawnBy: Manu; Engineer: Not shown in title block; Organization: Not shown in title block; Address1: Not shown in title block; Address2: Not shown in title block; Address3: Not shown in title block; Address4: Not shown in title block; DocumentNumber: 1; Revision: Use project parameter SCH_Rev; SheetNumber: 4; SheetTotal: 5; PageSetup: Record=PageOptions¦CenterHorizontal=True¦CenterVertical=True¦PrintScale=1.00¦XCorrection=1.00¦YCorrection=1.00¦PrintKind=0¦BorderSize=5000000¦LeftOffset=0¦BottomOffset=0¦Orientation=2¦PaperLength=1000¦PaperWidth=1000¦Scale=100¦PaperSource=15¦PrintQuality=600¦MediaType=1¦DitherType=10¦PaperKind=Letter¦PrintScaleMode=1
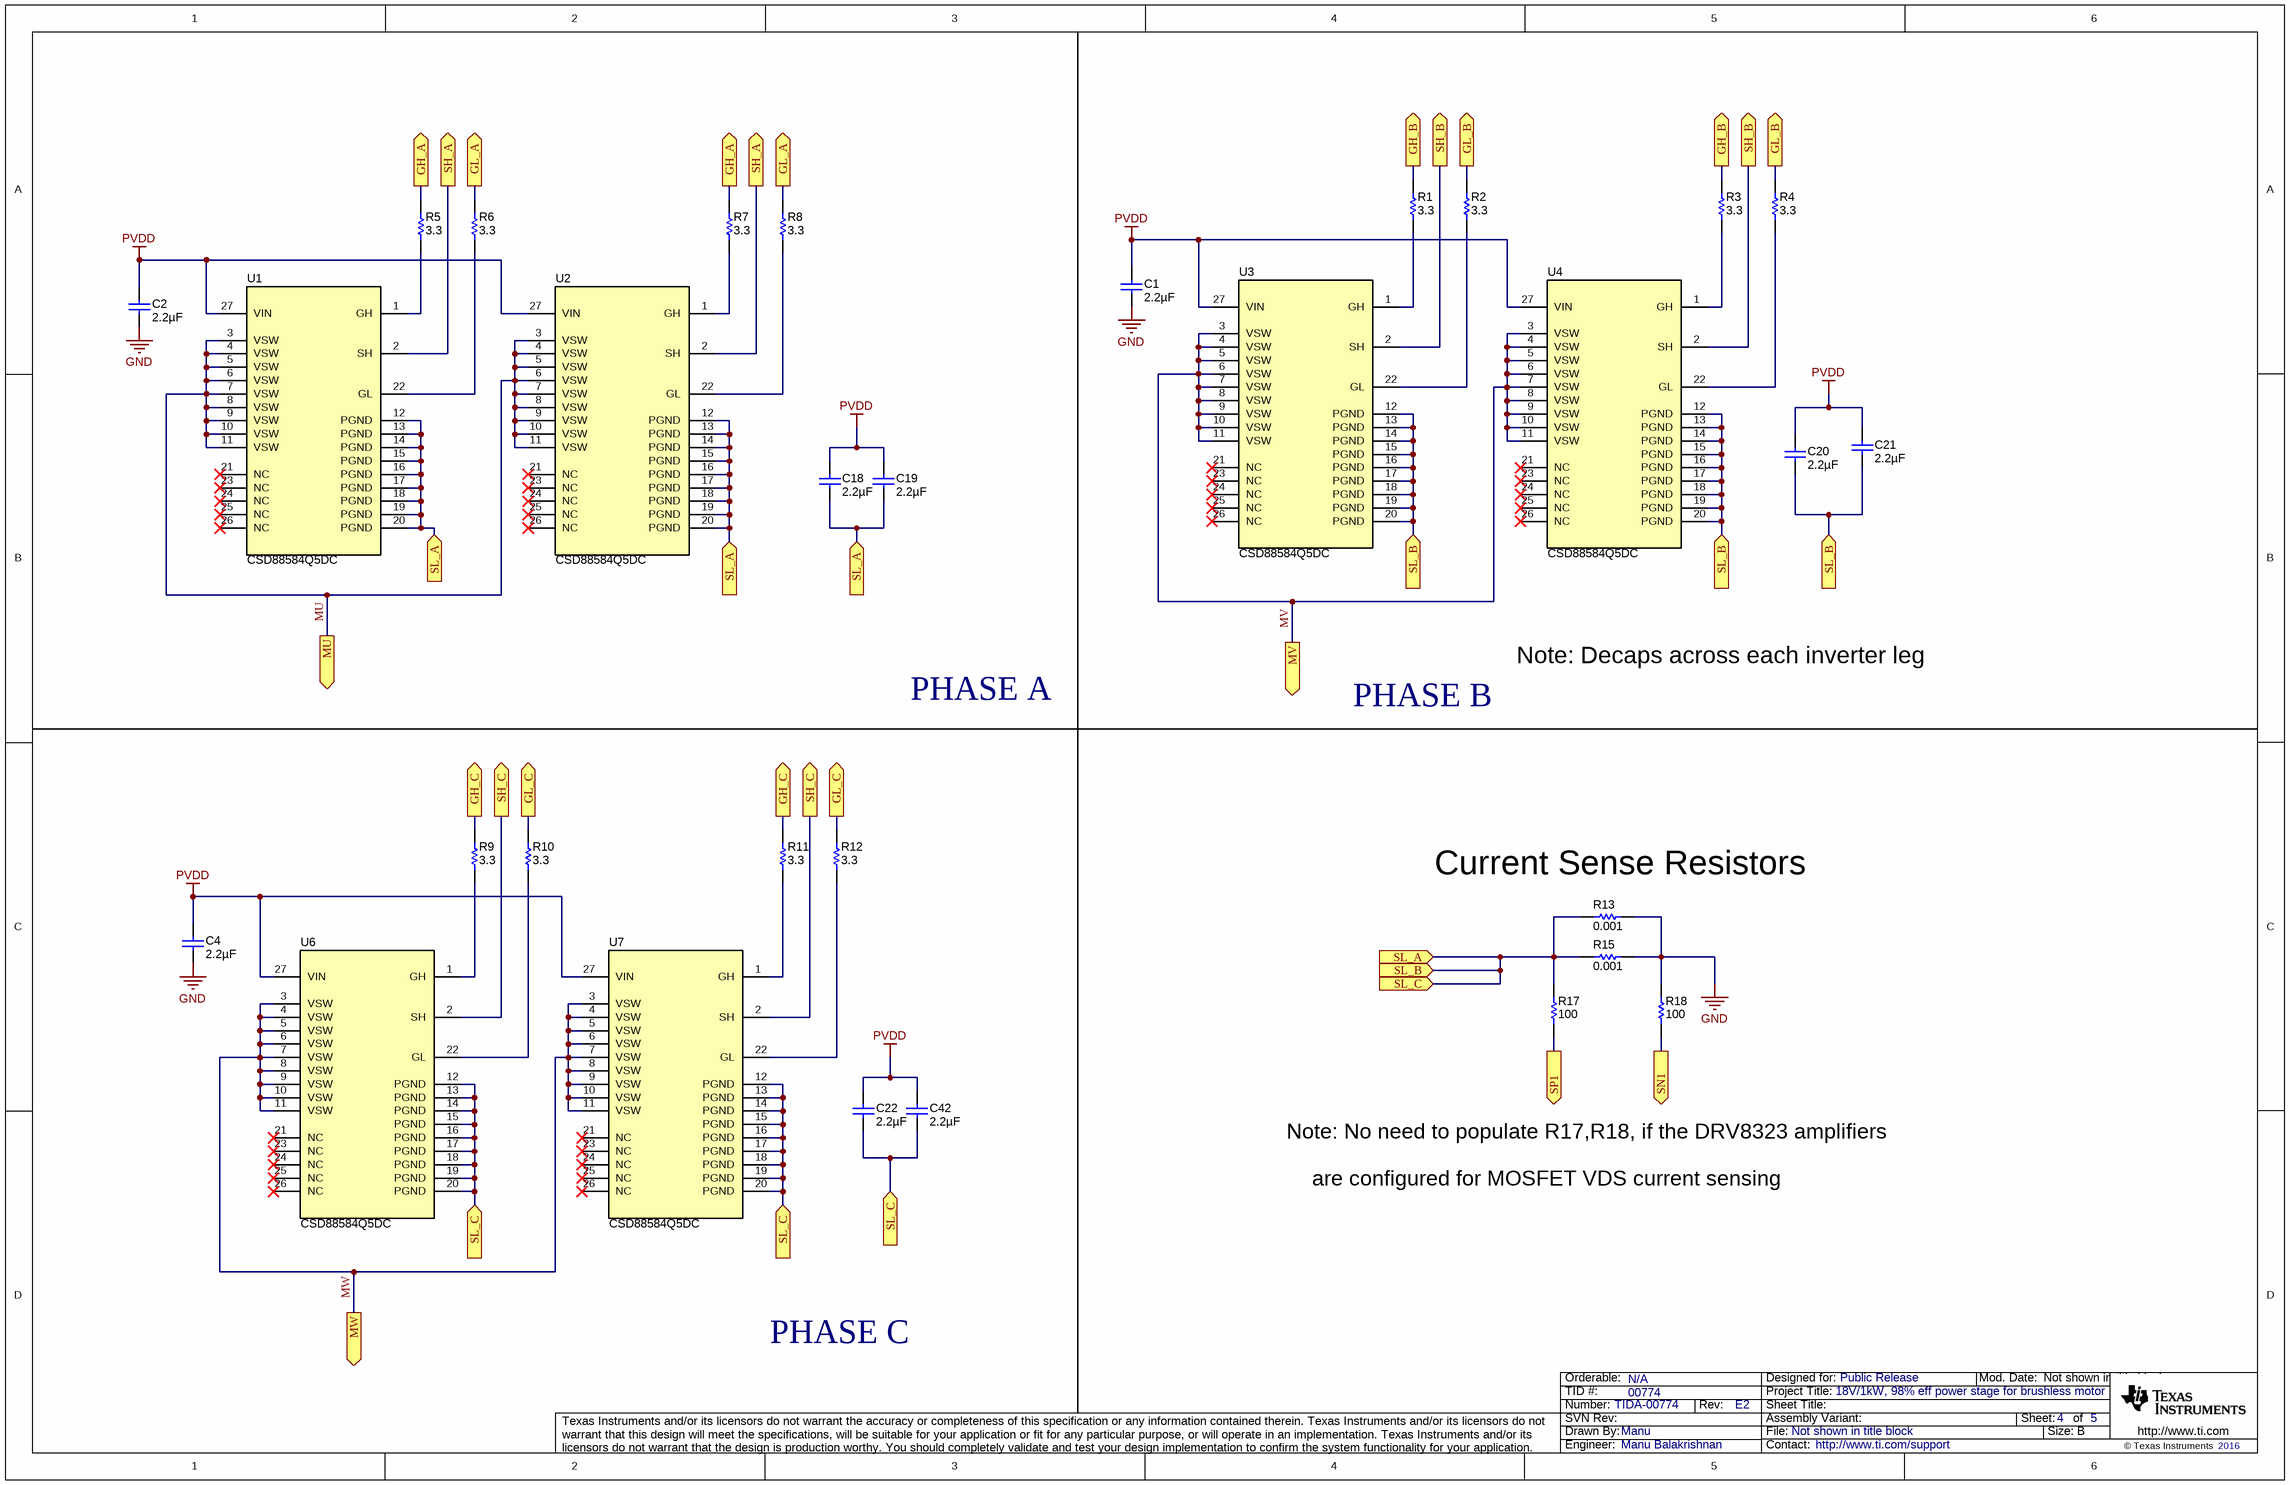
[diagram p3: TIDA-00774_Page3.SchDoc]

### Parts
C1  ValueDisplayed: 2.2µF  [1210]  (hidden comment: GRM32ER72A225KA35L)
C2  ValueDisplayed: 2.2µF  [1210]  (hidden comment: GRM32ER72A225KA35L)
C4  ValueDisplayed: 2.2µF  [1210]  (hidden comment: GRM32ER72A225KA35L)
C18  ValueDisplayed: 2.2µF  [1210]  (hidden comment: GRM32ER72A225KA35L)
C19  ValueDisplayed: 2.2µF  [1210]  (hidden comment: GRM32ER72A225KA35L)
C20  ValueDisplayed: 2.2µF  [1210]  (hidden comment: GRM32ER72A225KA35L)
C21  ValueDisplayed: 2.2µF  [1210]  (hidden comment: GRM32ER72A225KA35L)
C22  ValueDisplayed: 2.2µF  [1210_270]  (hidden comment: GRM32ER72A225KA35L)
C42  ValueDisplayed: 2.2µF  [1210]  (hidden comment: GRM32ER72A225KA35L)
R1  ValueDisplayed: 3.3  [0603]  (hidden comment: CRCW06033R30JNEA)
R2  ValueDisplayed: 3.3  [0603]  (hidden comment: CRCW06033R30JNEA)
R3  ValueDisplayed: 3.3  [0603]  (hidden comment: CRCW06033R30JNEA)
R4  ValueDisplayed: 3.3  [0603]  (hidden comment: CRCW06033R30JNEA)
R5  ValueDisplayed: 3.3  [0603]  (hidden comment: CRCW06033R30JNEA)
R6  ValueDisplayed: 3.3  [0603]  (hidden comment: CRCW06033R30JNEA)
R7  ValueDisplayed: 3.3  [0603]  (hidden comment: CRCW06033R30JNEA)
R8  ValueDisplayed: 3.3  [0603]  (hidden comment: CRCW06033R30JNEA)
R9  ValueDisplayed: 3.3  [0603]  (hidden comment: CRCW06033R30JNEA)
R10  ValueDisplayed: 3.3  [0603]  (hidden comment: CRCW06033R30JNEA)
R11  ValueDisplayed: 3.3  [0603]  (hidden comment: CRCW06033R30JNEA)
R12  ValueDisplayed: 3.3  [0603]  (hidden comment: CRCW06033R30JNEA)
R13  ValueDisplayed: 0.001  [2512]  (hidden comment: CSNL2512FT2L00)
R15  ValueDisplayed: 0.001  [2512]  (hidden comment: CSNL2512FT2L00)
R17  ValueDisplayed: 100  [0402]  (hidden comment: ERJ-2RKF1000X)
R18  ValueDisplayed: 100  [0402]  (hidden comment: ERJ-2RKF1000X)
U1  CSD88584Q5DC  [DMM0022A]
U2  CSD88584Q5DC  [DMM0022A]
U3  CSD88584Q5DC  [DMM0022A]
U4  CSD88584Q5DC  [DMM0022A]
U6  CSD88584Q5DC  [DMM0022A]
U7  CSD88584Q5DC  [DMM0022A]

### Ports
GH_A (out), GH_B (out), GH_C (out), GL_A (out), GL_B (out), GL_C (out), MU (out), MV (out), MW (out), SH_A (out), SH_B (out), SH_C (out), SL_A (in), SL_B (in), SL_C (in), SN1 (out), SP1 (out)

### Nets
GND: C1.2 C2.2 C4.2 R13.2 R15.2 R18.2
PVDD: C1.1 C2.1 C4.1 C18.1 C19.1 C20.1 C21.1 C22.1 C42.1 U1.27(VIN) U2.27(VIN) U3.27(VIN) U4.27(VIN) U6.27(VIN) U7.27(VIN)
GH_A: R5.2 R7.2 ; port GH_A
GH_B: R1.2 R3.2 ; port GH_B
GH_C: R9.2 R11.2 ; port GH_C
GL_A: R6.2 R8.2 ; port GL_A
GL_B: R2.2 R4.2 ; port GL_B
GL_C: R10.2 R12.2 ; port GL_C
MU: U1.3(VSW) U1.4(VSW) U1.5(VSW) U1.6(VSW) U1.7(VSW) U1.8(VSW) U1.9(VSW) U1.10(VSW) U1.11(VSW) U2.3(VSW) U2.4(VSW) U2.5(VSW) U2.6(VSW) U2.7(VSW) U2.8(VSW) U2.9(VSW) U2.10(VSW) U2.11(VSW) ; port MU
MV: U3.3(VSW) U3.4(VSW) U3.5(VSW) U3.6(VSW) U3.7(VSW) U3.8(VSW) U3.9(VSW) U3.10(VSW) U3.11(VSW) U4.3(VSW) U4.4(VSW) U4.5(VSW) U4.6(VSW) U4.7(VSW) U4.8(VSW) U4.9(VSW) U4.10(VSW) U4.11(VSW) ; port MV
MW: U6.3(VSW) U6.4(VSW) U6.5(VSW) U6.6(VSW) U6.7(VSW) U6.8(VSW) U6.9(VSW) U6.10(VSW) U6.11(VSW) U7.3(VSW) U7.4(VSW) U7.5(VSW) U7.6(VSW) U7.7(VSW) U7.8(VSW) U7.9(VSW) U7.10(VSW) U7.11(VSW) ; port MW
SH_A: U1.2(SH) U2.2(SH) ; port SH_A
SH_B: U3.2(SH) U4.2(SH) ; port SH_B
SH_C: U6.2(SH) U7.2(SH) ; port SH_C
SL_A: C18.2 C19.2 C20.2 C21.2 C22.2 C42.2 R13.1 R15.1 R17.2 U1.12(PGND) U1.13(PGND) U1.14(PGND) U1.15(PGND) U1.16(PGND) U1.17(PGND) U1.18(PGND) U1.19(PGND) U1.20(PGND) U2.12(PGND) U2.13(PGND) U2.14(PGND) U2.15(PGND) U2.16(PGND) U2.17(PGND) U2.18(PGND) U2.19(PGND) U2.20(PGND) U3.12(PGND) U3.13(PGND) U3.14(PGND) U3.15(PGND) U3.16(PGND) U3.17(PGND) U3.18(PGND) U3.19(PGND) U3.20(PGND) U4.12(PGND) U4.13(PGND) U4.14(PGND) U4.15(PGND) U4.16(PGND) U4.17(PGND) U4.18(PGND) U4.19(PGND) U4.20(PGND) U6.12(PGND) U6.13(PGND) U6.14(PGND) U6.15(PGND) U6.16(PGND) U6.17(PGND) U6.18(PGND) U6.19(PGND) U6.20(PGND) U7.12(PGND) U7.13(PGND) U7.14(PGND) U7.15(PGND) U7.16(PGND) U7.17(PGND) U7.18(PGND) U7.19(PGND) U7.20(PGND) ; port SL_A, port SL_B, port SL_C
SN1: R18.1 ; port SN1
SP1: R17.1 ; port SP1
NetR1_1: R1.1 U3.1(GH)
NetR2_1: R2.1 U3.22(GL)
NetR3_1: R3.1 U4.1(GH)
NetR4_1: R4.1 U4.22(GL)
NetR5_1: R5.1 U1.1(GH)
NetR6_1: R6.1 U1.22(GL)
NetR7_1: R7.1 U2.1(GH)
NetR8_1: R8.1 U2.22(GL)
NetR9_1: R9.1 U6.1(GH)
NetR10_1: R10.1 U6.22(GL)
NetR11_1: R11.1 U7.1(GH)
NetR12_1: R12.1 U7.22(GL)

Not connected (* = marked no-connect by the designer): U1 21(NC)* 23(NC)* 24(NC)* 25(NC)* 26(NC)*; U2 21(NC)* 23(NC)* 24(NC)* 25(NC)* 26(NC)*; U3 21(NC)* 23(NC)* 24(NC)* 25(NC)* 26(NC)*; U4 21(NC)* 23(NC)* 24(NC)* 25(NC)* 26(NC)*; U6 21(NC)* 23(NC)* 24(NC)* 25(NC)* 26(NC)*; U7 21(NC)* 23(NC)* 24(NC)* 25(NC)* 26(NC)*

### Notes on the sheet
- PHASE A
- Note: Decaps across each inverter leg
- PHASE B
- (near R13) Current Sense Resistors
- Note: No need to populate R17,R18, if the DRV8323 amplifiers
- are configured for MOSFET VDS current sensing
- PHASE C

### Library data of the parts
C1 C2 C4 C18-C21 C42 = GRM32ER72A225KA35L: as C41 on sheet TIDA-00774_Page1
C22 = GRM32ER72A225KA35L: CAP, CERM, 2.2 µF, 100 V, +/- 10%, X7R, 1210; Manufacturer: MuRata; Polarized: N; CompType: Capacitor; Value: 2.2uF; U/M: EA; Cap_F: 0.0000022; Tolerance_%: 10; ESR_ohm: 0.007; Value1: 0.007 ohm; VDC_V: 100; Value2: 100V; IRMS_A: 4.4; TaMin_C: -55; TaMax_C: 125; Cap_Case: 1210; AEC Category: Q200; SizeArea_mm2: 8; SizeAreaWB_mm2: 14.7; SizeX_mm: 3.2; SizeY_mm: 2.5; SizeZ_mm: 2.7
R1-R12 = CRCW06033R30JNEA: RES, 3.3, 5%, 0.1 W, 0603; Manufacturer: Vishay-Dale; CompType: Resistor; Value: 3.3; Value_Code: 3R30; Tolerance_%: 5; Power_W: 0.1; Value2: 0.1W; VDC_V: 75; TempCo: 200 ppm/C; SizeArea_mm2: 1.28; SizeX_mm: 1.6; SizeY_mm: 0.8; SizeZ_mm: 1; EIA_Code: E24; U/M: EA; AEC Category: Q200
R13 R15 = CSNL2512FT2L00: RES SMD 0.001 OHM 1% 5W 2512; PartNumber: CSS2H-2512R-1L00F; Manufacturer: Bourns Inc.; CompType: Resistor; Value: 0.001; Value_Code: 2L000; Tolerance_%: 1; Power_W: 5; Value2: 3W; VDC_V: 200; TempCo: 50 ppm/C; U/M: EA; AEC Category: Q200
R17 R18 = ERJ-2RKF1000X: as R50 on sheet TIDA-00774_Page2
U1-U4 U6 U7 = CSD88584Q5DC: 40 V Half-Bridge NexFE Power Block, DMM0022A; Alternate PartNumber: CSD88584Q5DCT; Manufacturer: Texas Instruments; SymbolCreator: Altium; SizeArea_mm2: 30; SizeAreaWB_mm2: 56; SizeX_mm: 5; SizeY_mm: 6; SizeZ_mm: 1.05; CompType: IC; U/M: EA

## Sheet TIDA-00774_Hardware.SchDoc
size 431 x 279 mm; Date: Not shown in title block; ApprovedBy: Not shown in title block; CheckedBy: Not shown in title block; Author: Not shown in title block; CompanyName: Not shown in title block; DrawnBy: Manu; Engineer: Not shown in title block; Organization: Not shown in title block; Address1: Not shown in title block; Address2: Not shown in title block; Address3: Not shown in title block; Address4: Not shown in title block; DocumentNumber: 1; Revision: Use project parameter SCH_Rev; SheetNumber: 5; SheetTotal: 5; PageSetup: Record=PageOptions¦CenterHorizontal=True¦CenterVertical=True¦PrintScale=1.00¦XCorrection=1.00¦YCorrection=1.00¦PrintKind=0¦BorderSize=5000000¦LeftOffset=0¦BottomOffset=0¦Orientation=2¦PaperLength=1000¦PaperWidth=1000¦Scale=100¦PaperSource=15¦PrintQuality=600¦MediaType=1¦DitherType=10¦PaperKind=Letter¦PrintScaleMode=1
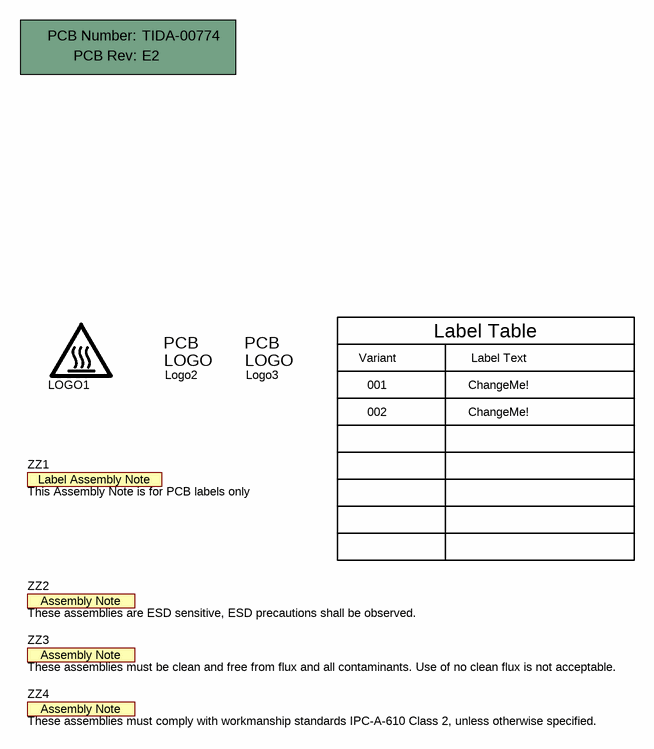
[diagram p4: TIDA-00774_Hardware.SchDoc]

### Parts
!PCB1  Printed Circuit Board  (value not drawn)  (mechanical)
LOGO1  CAUTION HOT SURFACE  [IEC_HotSurface_medium]  (value not drawn)  (no BOM)
Logo2  ESD Susceptible  [ESD_Overlay_small]  (value not drawn)  (no BOM)
Logo3  Pb-Free Symbol  [Pb-Free_Overlay_small]  (value not drawn)  (no BOM)
ZZ1  This Assembly Note is for PCB labels only  [AssemblyNoteLabel]  (no BOM)
ZZ2  These assemblies are ESD sensitive, ESD precautions shall be observed.  [AssemblyNote]  (no BOM)
ZZ3  These assemblies must be clean and free from flux and all contaminants. Use of no clean flux is not acceptable.  [AssemblyNote]  (no BOM)
ZZ4  These assemblies must comply with workmanship standards IPC-A-610 Class 2, unless otherwise specified.  [AssemblyNote]  (no BOM)

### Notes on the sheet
- Variant
- 001
- Label Table
- Label Text
- ChangeMe!
- 002

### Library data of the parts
!PCB1 = PCB: Manufacturer: Any; PartNumber: TIDA-00774; SymbolCreator: a0412235
LOGO1 = IEC_HotSurface: IEC 61010-1 Hot Surface Warning; SymbolCreator: a0412235
Logo2 = ESD_Susceptible: ESD Susceptible Symbol; SymbolCreator: a0412235
Logo3 = Pb-Free: SymbolCreator: a0412235
ZZ1 = AssemblyNoteLabel: SymbolCreator: a0412235
ZZ2-ZZ4 = AssemblyNote: SymbolCreator: codlsc

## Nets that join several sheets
3.3V: TIDA-00774_Page1 (R33.1 R36.1 R56.1), TIDA-00774_Page2 (19 pins)
GND: TIDA-00774_Page1 (21 pins), TIDA-00774_Page2 (35 pins), TIDA-00774_Page3 (6 pins)
PVDD: TIDA-00774_Page1 (12 pins), TIDA-00774_Page2 (C6.1 R16.2 U5.2), TIDA-00774_Page3 (15 pins)
CAL: TIDA-00774_Page1 (U8.31), TIDA-00774_Page2 (U9.23)
DC_FB: TIDA-00774_Page1 (C23.1 R23.1 R31.2), TIDA-00774_Page2 (U9.5)
EN_GATE: TIDA-00774_Page1 (U8.30), TIDA-00774_Page2 (J5.7 U9.3)
FAULT: TIDA-00774_Page1 (R36.2 U8.25), TIDA-00774_Page2 (R40.1 U9.2)
GH_A: TIDA-00774_Page1 (U8.6), TIDA-00774_Page3 (R5.2 R7.2)
GH_B: TIDA-00774_Page1 (U8.15), TIDA-00774_Page3 (R1.2 R3.2)
GH_C: TIDA-00774_Page1 (U8.16), TIDA-00774_Page3 (R9.2 R11.2)
GL_A: TIDA-00774_Page1 (U8.8), TIDA-00774_Page3 (R6.2 R8.2)
GL_B: TIDA-00774_Page1 (U8.13), TIDA-00774_Page3 (R2.2 R4.2)
GL_C: TIDA-00774_Page1 (U8.18), TIDA-00774_Page3 (R10.2 R12.2)
HA: TIDA-00774_Page1 (R25.1), TIDA-00774_Page2 (C40.1 R52.1 U9.19)
HB: TIDA-00774_Page1 (R28.1), TIDA-00774_Page2 (C39.1 R51.1 U9.18)
HC: TIDA-00774_Page1 (R30.1), TIDA-00774_Page2 (C38.1 R50.1 U9.20)
IA_IDC: TIDA-00774_Page1 (C43.1 R55.2), TIDA-00774_Page2 (J5.12 U9.6 U9.7)
IB: TIDA-00774_Page1 (C45.1 R54.2), TIDA-00774_Page2 (J5.13 U9.9)
IC: TIDA-00774_Page1 (C44.1 R53.2), TIDA-00774_Page2 (J5.14 U9.10)
INH_A: TIDA-00774_Page1 (U8.34), TIDA-00774_Page2 (J5.4 U9.16)
INH_B: TIDA-00774_Page1 (R29.1), TIDA-00774_Page2 (J5.2 U9.24)
INH_C: TIDA-00774_Page1 (U8.38), TIDA-00774_Page2 (J5.6 U9.32)
INL_A: TIDA-00774_Page1 (R27.1), TIDA-00774_Page2 (J5.3 U9.17)
INL_B: TIDA-00774_Page1 (R32.1), TIDA-00774_Page2 (J5.1 U9.25)
INL_C: TIDA-00774_Page1 (U8.39), TIDA-00774_Page2 (J5.5 U9.37)
SCLK: TIDA-00774_Page1 (R35.2), TIDA-00774_Page2 (J5.9 U9.13)
SCS: TIDA-00774_Page1 (U8.29), TIDA-00774_Page2 (J5.8 U9.14)
SDI: TIDA-00774_Page1 (R34.2), TIDA-00774_Page2 (J5.10 U9.12)
SDO: TIDA-00774_Page1 (R33.2 U8.26), TIDA-00774_Page2 (J5.11 U9.11)
SH_A: TIDA-00774_Page1 (U8.7), TIDA-00774_Page3 (U1.2 U2.2)
SH_B: TIDA-00774_Page1 (U8.14), TIDA-00774_Page3 (U3.2 U4.2)
SH_C: TIDA-00774_Page1 (U8.17), TIDA-00774_Page3 (U6.2 U7.2)
SL_A: TIDA-00774_Page1 (R24.1 R26.1 R57.1), TIDA-00774_Page3 (63 pins)
SN1: TIDA-00774_Page1 (C25.2 R57.2 U8.10), TIDA-00774_Page3 (R18.1)
SP1: TIDA-00774_Page1 (C25.1 U8.9), TIDA-00774_Page3 (R17.1)

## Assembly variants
001: not fitted C25 C46 C47 C48 R17 R18 R25 R28 R30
